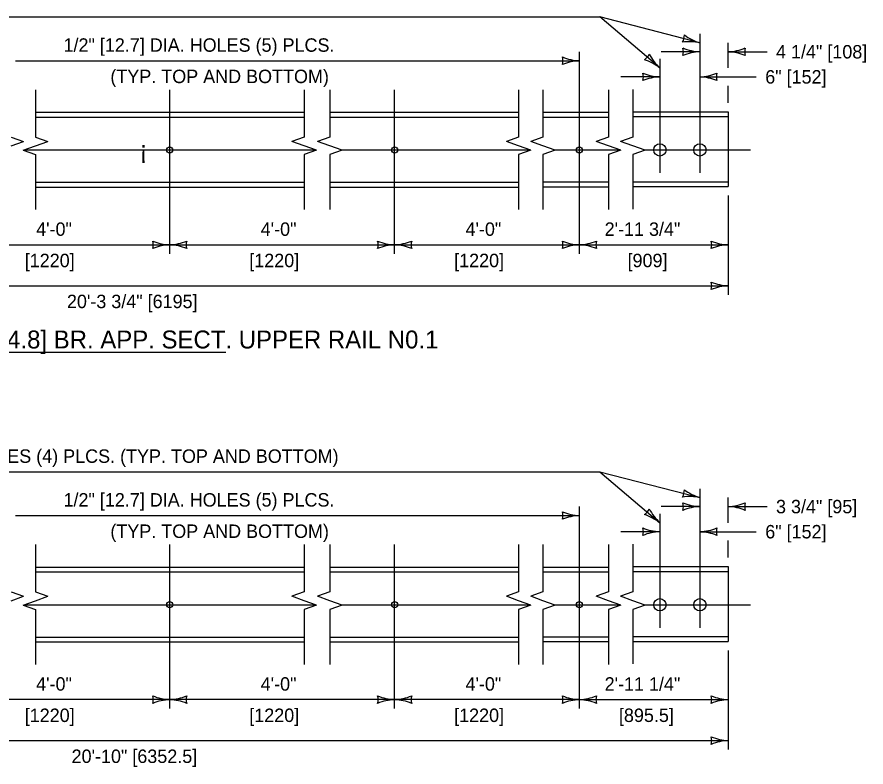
# Model space of a CAD drawing. Extents: x 49991.4 to 50021, y 49987.6 to 50011.4.
# Drawn here: x 50002.032 to 50005.825, y 49993.202 to 49996.553 of the extents above; entities that cross this region are included whole.
import ezdxf

# ---------------------------------------------------------------- set-up
doc = ezdxf.new("R2010")
doc.units = 0
for name, color, linetype in [('Level 1', 7, 'Continuous'), ('Level 2', 7, 'Continuous'), ('Level 3', 7, 'Continuous'), ('Level 4', 7, 'Continuous'), ('Level 5', 7, 'Continuous'), ('Level 6', 7, 'Continuous')]:
    doc.layers.add(name, color=color, linetype=linetype)

msp = doc.modelspace()

# ---------------------------------------------------------------- linework, layer by layer
at = {"layer": 'Level 1'}
for p, q in [((50002.1147, 49996.1275), (50003.3147, 49996.1275)), ((50003.4298, 49996.1275), (50004.2732, 49996.1275)), ((50004.3818, 49996.1275), (50004.6746, 49996.1275)), ((50004.7832, 49996.1296), (50005.2093, 49996.1296)), ((50005.2093, 49996.1296), (50005.2093, 49995.7949)), ((50002.1147, 49995.7928), (50003.3147, 49995.7928)), ((50003.4298, 49995.7928), (50004.2732, 49995.7928)), ((50004.6746, 49995.7928), (50004.3818, 49995.7928)), ((50004.7832, 49995.7949), (50005.2093, 49995.7949)), ((50002.1147, 49994.0958), (50003.3147, 49994.0958)), ((50003.4298, 49994.0958), (50004.2732, 49994.0958)), ((50004.3818, 49994.0958), (50004.6746, 49994.0958)), ((50004.7831, 49994.0979), (50005.2093, 49994.0979)), ((50005.2093, 49994.0979), (50005.2093, 49993.7632)), ((50002.1147, 49993.7611), (50003.3147, 49993.7611)), ((50003.4298, 49993.7611), (50004.2732, 49993.7611)), ((50004.6746, 49993.7611), (50004.3818, 49993.7611)), ((50004.7831, 49993.7632), (50005.2093, 49993.7632))]:
    msp.add_line(p, q, dxfattribs=at)
for centre, radius in [((50004.904, 49995.9589), 0.0274), ((50005.0828, 49995.9589), 0.0274), ((50002.7147, 49995.9589), 0.0137), ((50003.7192, 49995.9587), 0.0137), ((50004.5446, 49995.9589), 0.0137), ((50002.7147, 49993.9272), 0.0137), ((50003.7192, 49993.927), 0.0137), ((50004.5446, 49993.9272), 0.0137), ((50004.904, 49993.9272), 0.0274), ((50005.0828, 49993.9272), 0.0274)]:
    msp.add_circle(centre, radius, dxfattribs=at)
at = {"layer": 'Level 2'}
msp.add_line((50001.1852, 49995.0562), (50002.9646, 49995.0562), dxfattribs=at)
at = {"layer": 'Level 3'}
for p, q in [((50000.658, 49996.5529), (50004.6353, 49996.5529)), ((50005.0826, 49996.4375), (50004.6353, 49996.5529)), ((50004.9035, 49996.3254), (50004.6353, 49996.5529)), ((50005.2093, 49996.3254), (50005.2093, 49996.4375)), ((50005.0826, 49996.3975), (50004.9092, 49996.3975)), ((50005.2093, 49996.3975), (50005.3827, 49996.3975)), ((50002.0254, 49996.3575), (50004.5446, 49996.3575)), ((50004.9035, 49996.2854), (50004.7301, 49996.2854)), ((50005.0826, 49996.2854), (50005.3346, 49996.2854)), ((50005.2093, 49996.1696), (50005.2093, 49996.2454)), ((50005.2093, 49995.7549), (50005.2093, 49995.3122)), ((50001.7134, 49995.5352), (50002.7147, 49995.5352)), ((50002.7147, 49995.5352), (50003.7192, 49995.5352)), ((50003.7192, 49995.5352), (50004.5446, 49995.5352)), ((50004.5446, 49995.5352), (50005.2093, 49995.5352)), ((50000.084, 49995.3522), (50005.2093, 49995.3522)), ((50000.658, 49994.5212), (50004.6353, 49994.5212)), ((50004.6353, 49994.5212), (50005.0826, 49994.4058)), ((50004.6353, 49994.5212), (50004.9035, 49994.2936)), ((50005.2093, 49994.2936), (50005.2093, 49994.4058)), ((50005.0826, 49994.3658), (50004.9092, 49994.3658)), ((50005.2093, 49994.3658), (50005.3827, 49994.3658)), ((50002.0254, 49994.3258), (50004.5446, 49994.3258)), ((50004.9035, 49994.2536), (50004.7301, 49994.2536)), ((50005.0826, 49994.2536), (50005.3346, 49994.2536)), ((50005.2093, 49994.1379), (50005.2093, 49994.2136)), ((50005.2093, 49993.7232), (50005.2093, 49993.2805)), ((50002.7147, 49993.5035), (50001.7134, 49993.5035)), ((50003.7192, 49993.5035), (50002.7147, 49993.5035)), ((50004.5446, 49993.5035), (50003.7192, 49993.5035)), ((50004.5446, 49993.5035), (50005.2093, 49993.5035)), ((50000.084, 49993.3205), (50005.2093, 49993.3205))]:
    msp.add_line(p, q, dxfattribs=at)
for centre, radius, start, end in [((50004.9585, 49996.4695), 0.0548, 327.676, 3.3984), ((50005.147, 49996.6503), 0.2223, 232.9932, 253.1767), ((50005.0357, 49996.2093), 0.233, 78.3645, 97.6144), ((50005.0918, 49996.6197), 0.2223, 247.456, 267.6395), ((50004.9544, 49996.3975), 0.0548, 342.1388, 17.8612), ((50005.0941, 49996.1648), 0.233, 92.8273, 112.0772), ((50005.2002, 49996.6197), 0.2223, 272.3605, 292.544), ((50005.1978, 49996.1648), 0.233, 67.9228, 87.1727), ((50005.3375, 49996.3975), 0.0548, 162.1388, 197.8612), ((50004.5537, 49996.5796), 0.2223, 247.456, 267.6395), ((50004.4164, 49996.3575), 0.0548, 342.1388, 17.8612), ((50004.8057, 49996.4083), 0.0548, 301.8227, 337.545), ((50004.7617, 49996.1405), 0.233, 52.5112, 71.761), ((50005.0542, 49996.4888), 0.2223, 207.1399, 227.3234), ((50004.5561, 49996.1248), 0.233, 92.8273, 112.0772), ((50004.9126, 49996.5075), 0.2223, 247.456, 267.6395), ((50004.7753, 49996.2854), 0.0548, 342.1388, 17.8612), ((50004.915, 49996.0526), 0.233, 92.8273, 112.0772), ((50005.0711, 49996.5181), 0.233, 272.8273, 292.0772), ((50005.0735, 49996.0632), 0.2223, 67.456, 87.6395), ((50005.2109, 49996.2854), 0.0548, 162.1388, 197.8612), ((50002.7238, 49995.7573), 0.2223, 247.456, 267.6395), ((50002.5865, 49995.5352), 0.0548, 342.1388, 17.8612), ((50002.7262, 49995.3025), 0.233, 92.8273, 112.0772), ((50002.7032, 49995.7679), 0.233, 272.8273, 292.0772), ((50002.7055, 49995.3131), 0.2223, 67.456, 87.6395), ((50002.8429, 49995.5352), 0.0548, 162.1388, 197.8612), ((50003.7284, 49995.7573), 0.2223, 247.456, 267.6395), ((50003.591, 49995.5352), 0.0548, 342.1388, 17.8612), ((50003.7307, 49995.3025), 0.233, 92.8273, 112.0772), ((50003.7078, 49995.7679), 0.233, 272.8273, 292.0772), ((50003.7101, 49995.3131), 0.2223, 67.456, 87.6395), ((50003.8475, 49995.5352), 0.0548, 162.1388, 197.8612), ((50004.5537, 49995.7573), 0.2223, 247.456, 267.6395), ((50004.4164, 49995.5352), 0.0548, 342.1388, 17.8612), ((50004.5561, 49995.3025), 0.233, 92.8273, 112.0772), ((50004.5331, 49995.7679), 0.233, 272.8273, 292.0772), ((50004.5354, 49995.3131), 0.2223, 67.456, 87.6395), ((50004.6728, 49995.5352), 0.0548, 162.1388, 197.8612), ((50005.2185, 49995.7573), 0.2223, 247.456, 267.6395), ((50005.0811, 49995.5352), 0.0548, 342.1388, 17.8612), ((50005.2208, 49995.3025), 0.233, 92.8273, 112.0772), ((50005.2185, 49995.5743), 0.2223, 247.456, 267.6395), ((50005.0811, 49995.3522), 0.0548, 342.1388, 17.8612), ((50005.2208, 49995.1195), 0.233, 92.8273, 112.0772), ((50004.9585, 49994.4378), 0.0548, 327.6711, 3.3935), ((50005.147, 49994.6186), 0.2223, 232.9883, 253.1718), ((50005.0356, 49994.1776), 0.233, 78.3596, 97.6094), ((50004.8057, 49994.3766), 0.0548, 301.8176, 337.5399), ((50005.0542, 49994.4571), 0.2223, 207.1347, 227.3183), ((50005.0918, 49994.5879), 0.2223, 247.456, 267.6395), ((50004.9544, 49994.3658), 0.0548, 342.1388, 17.8612), ((50005.0941, 49994.1331), 0.233, 92.8273, 112.0772), ((50005.2002, 49994.5879), 0.2223, 272.3605, 292.544), ((50005.1978, 49994.1331), 0.233, 67.9228, 87.1727), ((50005.3375, 49994.3658), 0.0548, 162.1388, 197.8612), ((50004.5538, 49994.5479), 0.2223, 247.456, 267.6395), ((50004.4164, 49994.3258), 0.0548, 342.1388, 17.8612), ((50004.5561, 49994.0931), 0.233, 92.8273, 112.0772), ((50004.7617, 49994.1088), 0.233, 52.506, 71.7559), ((50004.9126, 49994.4758), 0.2223, 247.456, 267.6395), ((50004.7753, 49994.2536), 0.0548, 342.1388, 17.8612), ((50004.915, 49994.0209), 0.233, 92.8273, 112.0772), ((50005.0711, 49994.4863), 0.233, 272.8273, 292.0772), ((50005.0735, 49994.0315), 0.2223, 67.456, 87.6395), ((50005.2109, 49994.2536), 0.0548, 162.1388, 197.8612), ((50002.7238, 49993.7256), 0.2223, 247.456, 267.6395), ((50002.5865, 49993.5035), 0.0548, 342.1388, 17.8612), ((50002.7032, 49993.7362), 0.233, 272.8273, 292.0772), ((50002.8429, 49993.5035), 0.0548, 162.1388, 197.8612), ((50003.7284, 49993.7256), 0.2223, 247.456, 267.6395), ((50003.591, 49993.5035), 0.0548, 342.1388, 17.8612), ((50003.7078, 49993.7362), 0.233, 272.8273, 292.0772), ((50003.8475, 49993.5035), 0.0548, 162.1388, 197.8612), ((50004.5538, 49993.7256), 0.2223, 247.456, 267.6395), ((50004.4164, 49993.5035), 0.0548, 342.1388, 17.8612), ((50004.5331, 49993.7362), 0.233, 272.8273, 292.0772), ((50004.6728, 49993.5035), 0.0548, 162.1388, 197.8612), ((50005.2185, 49993.7256), 0.2223, 247.456, 267.6395), ((50005.0811, 49993.5035), 0.0548, 342.1388, 17.8612), ((50002.7262, 49993.2708), 0.233, 92.8273, 112.0772), ((50002.7055, 49993.2813), 0.2223, 67.456, 87.6395), ((50003.7307, 49993.2708), 0.233, 92.8273, 112.0772), ((50003.7101, 49993.2813), 0.2223, 67.456, 87.6395), ((50004.5561, 49993.2708), 0.233, 92.8273, 112.0772), ((50004.5354, 49993.2813), 0.2223, 67.456, 87.6395), ((50005.2208, 49993.2708), 0.233, 92.8273, 112.0772), ((50005.2185, 49993.5426), 0.2223, 247.456, 267.6395), ((50005.0811, 49993.3205), 0.0548, 342.1388, 17.8612), ((50005.2208, 49993.0878), 0.233, 92.8273, 112.0772)]:
    msp.add_arc(centre, radius, start, end, dxfattribs=at)
at = {"layer": 'Level 4'}
for p, q in [((50002.1147, 49996.1059), (50003.3147, 49996.1059)), ((50003.4298, 49996.1059), (50004.2732, 49996.1059)), ((50004.3818, 49996.1059), (50004.6746, 49996.1059)), ((50004.7832, 49996.1081), (50005.2093, 49996.1081)), ((50002.1147, 49995.8143), (50003.3147, 49995.8143)), ((50003.4298, 49995.8143), (50004.2732, 49995.8143)), ((50004.6746, 49995.8143), (50004.3818, 49995.8143)), ((50004.7832, 49995.8165), (50005.2093, 49995.8165)), ((50002.1147, 49994.0742), (50003.3147, 49994.0742)), ((50003.4298, 49994.0742), (50004.2732, 49994.0742)), ((50004.3818, 49994.0742), (50004.6746, 49994.0742)), ((50004.7831, 49994.0764), (50005.2093, 49994.0764)), ((50002.1147, 49993.7826), (50003.3147, 49993.7826)), ((50003.4298, 49993.7826), (50004.2732, 49993.7826)), ((50004.6746, 49993.7826), (50004.3818, 49993.7826)), ((50004.7831, 49993.7848), (50005.2093, 49993.7848))]:
    msp.add_line(p, q, dxfattribs=at)
at = {"layer": 'Level 5'}
for p, q in [((50005.0826, 49996.4775), (50005.0826, 49995.8565)), ((50004.5446, 49995.4952), (50004.5446, 49996.3975)), ((50004.9035, 49996.3653), (50004.9035, 49995.8565)), ((50002.7147, 49995.4952), (50002.7147, 49996.2275)), ((50003.7192, 49995.4952), (50003.7192, 49996.2275)), ((50002.0623, 49995.9587), (50003.367, 49995.9587)), ((50003.4822, 49995.9587), (50004.3256, 49995.9587)), ((50004.4342, 49995.9587), (50004.7269, 49995.9587)), ((50004.8355, 49995.9587), (50005.3093, 49995.9587)), ((50005.0826, 49994.4458), (50005.0826, 49993.8248)), ((50004.5446, 49993.4635), (50004.5446, 49994.3658)), ((50004.9035, 49994.3336), (50004.9035, 49993.8248)), ((50002.7147, 49993.4635), (50002.7147, 49994.1958)), ((50003.7192, 49993.4635), (50003.7192, 49994.1958)), ((50002.0623, 49993.927), (50003.367, 49993.927)), ((50003.4821, 49993.927), (50004.3256, 49993.927)), ((50004.4342, 49993.927), (50004.7269, 49993.927)), ((50004.8354, 49993.927), (50005.3093, 49993.927))]:
    msp.add_line(p, q, dxfattribs=at)
at = {"layer": 'Level 6'}
for p, q in [((50002.1147, 49996.2275), (50002.1147, 49996.016)), ((50003.3147, 49996.2275), (50003.3147, 49996.016)), ((50003.4298, 49996.2275), (50003.4298, 49996.016)), ((50004.2732, 49996.2275), (50004.2732, 49996.016)), ((50004.3818, 49996.2275), (50004.3818, 49996.016)), ((50004.6746, 49996.2275), (50004.6746, 49996.016)), ((50004.7832, 49996.2296), (50004.7832, 49996.016)), ((50002.0061, 49996.016), (50002.0609, 49995.9966)), ((50002.0061, 49995.9772), (50002.0609, 49995.9966)), ((50002.1147, 49996.016), (50002.1695, 49995.9966)), ((50002.1147, 49995.9772), (50002.1695, 49995.9966)), ((50003.3147, 49996.016), (50003.2599, 49995.9966)), ((50003.3147, 49995.9772), (50003.2599, 49995.9966)), ((50003.4298, 49996.016), (50003.375, 49995.9966)), ((50003.4298, 49995.9772), (50003.375, 49995.9966)), ((50004.2732, 49996.016), (50004.2184, 49995.9966)), ((50004.2732, 49995.9772), (50004.2184, 49995.9966)), ((50004.3818, 49996.016), (50004.327, 49995.9966)), ((50004.3818, 49995.9772), (50004.327, 49995.9966)), ((50004.6746, 49996.016), (50004.6198, 49995.9966)), ((50004.6746, 49995.9772), (50004.6198, 49995.9966)), ((50004.7832, 49996.016), (50004.7284, 49995.9966)), ((50004.7832, 49995.9772), (50004.7284, 49995.9966)), ((50002.0599, 49995.9578), (50002.1147, 49995.9772)), ((50002.0599, 49995.9578), (50002.1147, 49995.9383)), ((50003.3695, 49995.9578), (50003.3147, 49995.9772)), ((50003.3695, 49995.9578), (50003.3147, 49995.9383)), ((50003.4846, 49995.9578), (50003.4298, 49995.9772)), ((50003.4846, 49995.9578), (50003.4298, 49995.9383)), ((50004.328, 49995.9578), (50004.2732, 49995.9772)), ((50004.328, 49995.9578), (50004.2732, 49995.9383)), ((50004.4366, 49995.9578), (50004.3818, 49995.9772)), ((50004.4366, 49995.9578), (50004.3818, 49995.9383)), ((50004.7294, 49995.9578), (50004.6746, 49995.9772)), ((50004.7294, 49995.9578), (50004.6746, 49995.9383)), ((50004.838, 49995.9578), (50004.7832, 49995.9772)), ((50004.838, 49995.9578), (50004.7832, 49995.9383)), ((50002.1147, 49995.9383), (50002.1147, 49995.6928)), ((50003.3147, 49995.9383), (50003.3147, 49995.6928)), ((50003.4298, 49995.9383), (50003.4298, 49995.6928)), ((50004.2732, 49995.9383), (50004.2732, 49995.6928)), ((50004.3818, 49995.9383), (50004.3818, 49995.6928)), ((50004.6746, 49995.9383), (50004.6746, 49995.6928)), ((50004.7832, 49995.9383), (50004.7832, 49995.6949)), ((50004.7831, 49994.1979), (50004.7831, 49993.9843)), ((50002.1147, 49994.1958), (50002.1147, 49993.9843)), ((50003.3147, 49994.1958), (50003.3147, 49993.9843)), ((50003.4298, 49994.1958), (50003.4298, 49993.9843)), ((50004.2732, 49994.1958), (50004.2732, 49993.9843)), ((50004.3818, 49994.1958), (50004.3818, 49993.9843)), ((50004.6746, 49994.1958), (50004.6746, 49993.9843)), ((50002.0061, 49993.9843), (50002.0609, 49993.9649)), ((50002.1147, 49993.9843), (50002.1695, 49993.9649)), ((50003.3147, 49993.9843), (50003.2599, 49993.9649)), ((50003.4298, 49993.9843), (50003.375, 49993.9649)), ((50004.2732, 49993.9843), (50004.2184, 49993.9649)), ((50004.3818, 49993.9843), (50004.327, 49993.9649)), ((50004.6746, 49993.9843), (50004.6198, 49993.9649)), ((50004.7831, 49993.9843), (50004.7283, 49993.9649)), ((50002.0061, 49993.9455), (50002.0609, 49993.9649)), ((50002.0599, 49993.9261), (50002.1147, 49993.9455)), ((50002.1147, 49993.9455), (50002.1695, 49993.9649)), ((50003.3147, 49993.9455), (50003.2599, 49993.9649)), ((50003.3695, 49993.9261), (50003.3147, 49993.9455)), ((50003.4298, 49993.9455), (50003.375, 49993.9649)), ((50003.4846, 49993.9261), (50003.4298, 49993.9455)), ((50004.2732, 49993.9455), (50004.2184, 49993.9649)), ((50004.328, 49993.9261), (50004.2732, 49993.9455)), ((50004.3818, 49993.9455), (50004.327, 49993.9649)), ((50004.4366, 49993.9261), (50004.3818, 49993.9455)), ((50004.6746, 49993.9455), (50004.6198, 49993.9649)), ((50004.7294, 49993.9261), (50004.6746, 49993.9455)), ((50004.7831, 49993.9455), (50004.7283, 49993.9649)), ((50004.8379, 49993.9261), (50004.7831, 49993.9455)), ((50002.0599, 49993.9261), (50002.1147, 49993.9066)), ((50002.1147, 49993.9066), (50002.1147, 49993.6611)), ((50003.3695, 49993.9261), (50003.3147, 49993.9066)), ((50003.3147, 49993.9066), (50003.3147, 49993.6611)), ((50003.4846, 49993.9261), (50003.4298, 49993.9066)), ((50003.4298, 49993.9066), (50003.4298, 49993.6611)), ((50004.328, 49993.9261), (50004.2732, 49993.9066)), ((50004.2732, 49993.9066), (50004.2732, 49993.6611)), ((50004.4366, 49993.9261), (50004.3818, 49993.9066)), ((50004.3818, 49993.9066), (50004.3818, 49993.6611)), ((50004.7294, 49993.9261), (50004.6746, 49993.9066)), ((50004.6746, 49993.9066), (50004.6746, 49993.6611)), ((50004.8379, 49993.9261), (50004.7831, 49993.9066)), ((50004.7831, 49993.9066), (50004.7831, 49993.6632))]:
    msp.add_line(p, q, dxfattribs=at)

# ---------------------------------------------------------------- texts
at = {"layer": 'Level 2'}
for s, height, p in [(' 1/2" [12.7] DIA. HOLES (5) PLCS.', 0.06, (50002.2179, 49996.3975)), ('4 1/4" [108]', 0.06, (50005.4227, 49996.3675)), ('(TYP. TOP AND BOTTOM)', 0.06, (50002.4495, 49996.2575)), ('6" [152]', 0.06, (50005.3746, 49996.2554)), ('¡', 0.08, (50002.5793, 49995.9189)), ('2\'-11 3/4"', 0.06, (50004.6572, 49995.5752)), ('4\'-0"', 0.06, (50002.1179, 49995.5752)), ('4\'-0"', 0.06, (50003.1209, 49995.5752)), ('4\'-0"', 0.06, (50004.0358, 49995.5752)), ('[1220]', 0.06, (50002.067, 49995.4352)), ('[1220]', 0.06, (50003.0699, 49995.4352)), ('[1220]', 0.06, (50003.9849, 49995.4352)), ('[909]', 0.06, (50004.7596, 49995.4352)), ('20\'-3 3/4" [6195]', 0.06, (50002.2555, 49995.2522)), ('TS6 x 6 x 3/16 [TS152 x 152 x 4.8] BR. APP. SECT. UPPER RAIL N0.1', 0.08, (50000.5196, 49995.0722)), ('1" [25.4] DIA. HOLES (4) PLCS. (TYP. TOP AND BOTTOM)', 0.06, (50001.3272, 49994.5612)), (' 1/2" [12.7] DIA. HOLES (5) PLCS.', 0.06, (50002.2179, 49994.3658)), ('3 3/4" [95]', 0.06, (50005.4227, 49994.3358)), ('(TYP. TOP AND BOTTOM)', 0.06, (50002.4495, 49994.2258)), ('6" [152]', 0.06, (50005.3746, 49994.2236)), ('4\'-0"', 0.06, (50002.1179, 49993.5435)), ('4\'-0"', 0.06, (50003.1209, 49993.5435)), ('4\'-0"', 0.06, (50004.0358, 49993.5435)), ('2\'-11 1/4"', 0.06, (50004.6572, 49993.5435)), ('[1220]', 0.06, (50002.067, 49993.4035)), ('[1220]', 0.06, (50003.0699, 49993.4035)), ('[1220]', 0.06, (50003.9849, 49993.4035)), ('[895.5]', 0.06, (50004.7211, 49993.4035)), ('20\'-10" [6352.5]', 0.06, (50002.2763, 49993.2205))]:
    msp.add_text(s, height=height, dxfattribs=at).set_placement(p)

doc.saveas('drawing.dxf')
